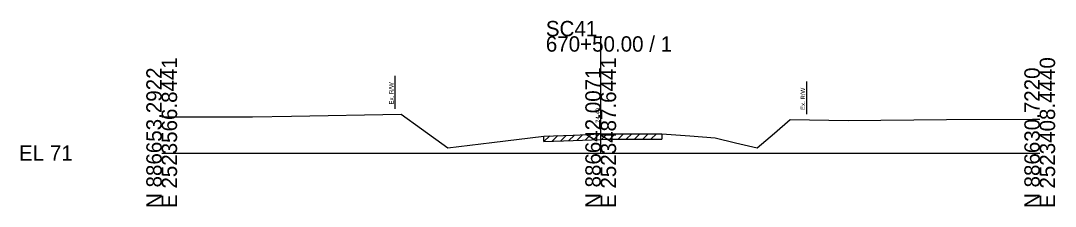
# Model space of a CAD drawing. Extents: x -26 to 183, y -10 to 24021.
# Drawn here: x -25.7 to 162.8, y 2990.3 to 3024.1 of the extents above; entities that cross this region are included whole.
import ezdxf

# ---------------------------------------------------------------- set-up
doc = ezdxf.new("R2010")
doc.units = 0
for name, color, linetype in [('RD_GPK_XS_Cell', 7, 'Continuous'), ('RD_XS_ExGround', 7, 'Continuous'), ('RD_XS_ExPaveRet', 7, 'Continuous'), ('RD_XS_ExRW', 7, 'Continuous'), ('RD_XS_TX_Elev_EX', 7, 'Continuous')]:
    doc.layers.add(name, color=color, linetype=linetype)

msp = doc.modelspace()

# ---------------------------------------------------------------- linework, layer by layer
at = {"layer": 'RD_GPK_XS_Cell'}
for p, q in [((80, 3000), (80, 3021.29)), ((0, 3000), (80, 3000)), ((80, 3000), (160, 3000))]:
    msp.add_line(p, q, dxfattribs=at)
at = {"layer": 'RD_XS_ExGround'}
for p, q in [((23.66, 3006.72), (43.61, 3007.1)), ((43.61, 3007.1), (47.37, 3004.41)), ((0, 3006.64), (16.55, 3006.59)), ((16.55, 3006.59), (23.66, 3006.72)), ((111.66, 3003.62), (114.55, 3006.12)), ((114.55, 3006.12), (125.09, 3005.95)), ((125.09, 3005.95), (143.03, 3006.14)), ((143.03, 3006.14), (158.66, 3006.16)), ((158.66, 3006.16), (160, 3006.16)), ((47.37, 3004.41), (52.13, 3000.98)), ((74.96, 3003.29), (80, 3003.49)), ((80, 3003.49), (80.99, 3003.53)), ((80.99, 3003.53), (85.8, 3003.54)), ((85.8, 3003.54), (91.13, 3003.54)), ((91.13, 3003.54), (96.23, 3003.13)), ((108.52, 3000.97), (111.66, 3003.62)), ((52.13, 3000.98), (60.19, 3001.92)), ((60.19, 3001.92), (69.66, 3003.09)), ((69.66, 3003.09), (74.96, 3003.29)), ((96.23, 3003.13), (100.86, 3002.8)), ((100.86, 3002.8), (104.58, 3001.9)), ((104.58, 3001.9), (108.52, 3000.97))]:
    msp.add_line(p, q, dxfattribs=at)
at = {"layer": 'RD_XS_ExPaveRet'}
for p, q in [((75.66, 3002.32), (76.7, 3003.36)), ((77.16, 3002.38), (78.2, 3003.42)), ((78.66, 3002.44), (79.7, 3003.48)), ((80.16, 3002.5), (81.19, 3003.53)), ((81.66, 3002.53), (82.66, 3003.53)), ((83.16, 3002.53), (84.16, 3003.53)), ((84.66, 3002.53), (85.66, 3003.54)), ((86.16, 3002.54), (87.16, 3003.54)), ((87.66, 3002.54), (88.66, 3003.54)), ((89.16, 3002.54), (90.16, 3003.54)), ((91.13, 3003.54), (91.13, 3002.54)), ((69.66, 3002.09), (70.7, 3003.13)), ((69.66, 3002.09), (69.66, 3003.09)), ((69.66, 3002.09), (74.96, 3002.29)), ((71.16, 3002.15), (72.2, 3003.19)), ((72.66, 3002.2), (73.7, 3003.24)), ((74.16, 3002.26), (75.2, 3003.3)), ((74.96, 3002.29), (80, 3002.49)), ((80, 3002.49), (80.99, 3002.53)), ((80.99, 3002.53), (85.8, 3002.54)), ((85.8, 3002.54), (91.13, 3002.54))]:
    msp.add_line(p, q, dxfattribs=at)
at = {"layer": 'RD_XS_ExRW'}
for p, q in [((42.5, 3014.08), (42.5, 3008.08)), ((117.5, 3013.07), (117.5, 3007.07))]:
    msp.add_line(p, q, dxfattribs=at)

# ---------------------------------------------------------------- texts
at = {"layer": 'RD_GPK_XS_Cell'}
for s, p in [('SC41', (70, 3021.29)), ('670+50.00 / 1', (70, 3018.49)), ('EL 71', (-26, 2998.6))]:
    msp.add_text(s, height=2.8, dxfattribs=at).set_placement(p)
for s, p in [('E 2523566.8441', (2.8, 2990)), ('E 2523487.6441', (82.8, 2990)), ('E 2523408.4440', (162.8, 2990)), ('N 886653.2922', (0, 2990)), ('N 886642.0071', (80, 2990)), ('N 886630.7220', (160, 2990))]:
    msp.add_text(s, height=2.8, rotation=90, dxfattribs=at).set_placement(p)
at = {"layer": 'RD_XS_ExRW'}
for p in [(42.25, 3008.86), (117.25, 3007.86)]:
    msp.add_text('Ex. R/W ', height=0.8, rotation=90, dxfattribs=at).set_placement(p)
at = {"layer": 'RD_XS_TX_Elev_EX'}
msp.add_text('74.49', height=0.8, rotation=90, dxfattribs=at).set_placement((79.9, 3005.49))

doc.saveas('drawing.dxf')
